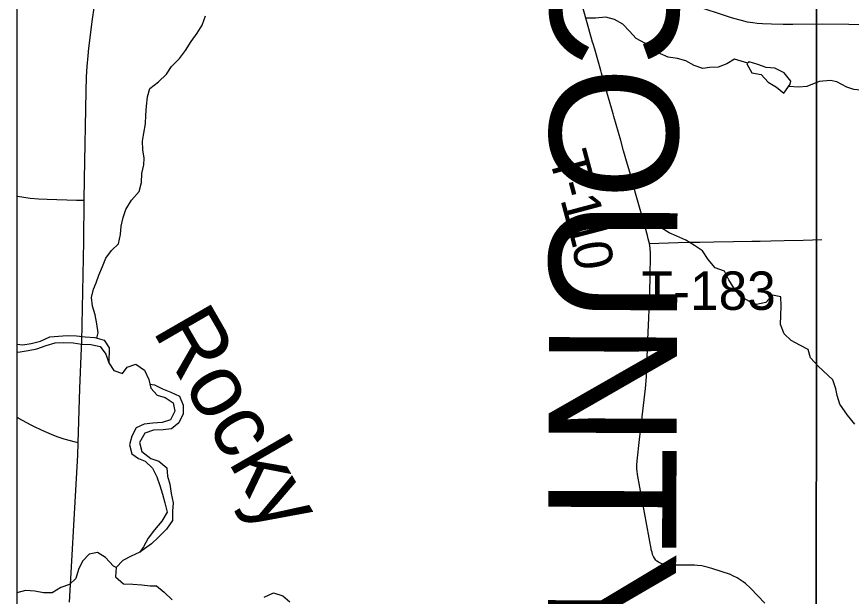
# Model space of a CAD drawing. Extents: x 0 to 34, y 0 to 22.
# Drawn here: x 2.1 to 3.335, y 16.53 to 17.388 of the extents above; entities that cross this region are included whole.
import ezdxf

# ---------------------------------------------------------------- set-up
doc = ezdxf.new("R2010")
doc.units = 0
for name, color, linetype in [('Default', 7, 'Continuous'), ('GM_X_County_Road', 7, 'Continuous'), ('GM_X_County_Text', 7, 'Continuous'), ('GM_X_Minor_Lake', 7, 'Continuous'), ('GM_X_Minor_River', 7, 'Continuous'), ('GM_X_Minor_River_Text', 7, 'Continuous'), ('GM_X_Township_Road', 7, 'Continuous'), ('GM_X_Township_Road_Text', 7, 'Continuous'), ('SH_Cut_Line', 7, 'Continuous'), ('SH_Data', 7, 'Continuous')]:
    doc.layers.add(name, color=color, linetype=linetype)

msp = doc.modelspace()

# ---------------------------------------------------------------- linework, layer by layer
at = {"layer": 'Default'}
msp.add_lwpolyline([(3.2826, 20.9), (2.1, 20.9), (2.1, 15.8248), (3.2829, 15.8433), (3.2832, 16.3898), (3.2835, 17.0107), (3.2837, 17.3796), (3.2907, 18.4315), (3.2904, 19.1173), (3.2901, 19.68), (3.2888, 19.8918), (3.2845, 20.5998), (3.2843, 20.6124)], close=True, dxfattribs=at)
msp.add_lwpolyline([(8.1749, 20.9), (3.2826, 20.9), (3.2843, 20.6124), (3.2845, 20.5998), (3.2888, 19.8918), (3.2901, 19.68), (3.2904, 19.1173), (3.2907, 18.4315), (3.2837, 17.3796), (3.2835, 17.0107), (3.2832, 16.3898), (3.2829, 15.8433), (3.425, 15.8449), (3.4609, 15.8448), (3.6703, 15.8472), (4.3446, 15.8524), (4.6273, 15.8569)], dxfattribs=at)
at = {"layer": 'GM_X_County_Road'}
msp.add_lwpolyline([(2.1781, 16.5218), (2.1849, 16.6442), (2.1903, 16.7391), (2.1912, 16.7577), (2.1934, 16.8382), (2.1958, 16.898), (2.1962, 16.9076), (2.1993, 17.0555), (2.2001, 17.1166), (2.2004, 17.148), (2.2028, 17.2783), (2.2034, 17.2994), (2.2041, 17.3149), (2.2056, 17.3304), (2.2069, 17.3417), (2.2122, 17.3845), (2.2146, 17.4013)], dxfattribs=at)
at = {"layer": 'GM_X_Minor_Lake'}
for points in [[(3.1841, 17.3218), (3.1807, 17.3184), (3.188, 17.3055), (3.2017, 17.303), (3.2121, 17.2913), (3.2247, 17.2839), (3.2351, 17.2752), (3.2448, 17.2883)], [(3.2448, 17.2883), (3.2459, 17.2929), (3.2359, 17.3053), (3.2222, 17.3124), (3.2092, 17.313), (3.197, 17.3174), (3.1841, 17.3218)], [(3.2448, 17.2883), (3.2459, 17.2929), (3.2359, 17.3053), (3.2222, 17.3124), (3.2092, 17.313), (3.197, 17.3174), (3.1841, 17.3218)]]:
    msp.add_lwpolyline(points, dxfattribs=at)
at = {"layer": 'GM_X_Minor_River'}
for points in [[(2.2187, 16.9127), (2.2205, 16.9202), (2.2186, 16.9338), (2.2163, 16.9468), (2.2121, 16.9597), (2.2109, 16.9726), (2.2139, 16.9848), (2.2177, 16.9943), (2.2215, 17.0057), (2.2272, 17.0187), (2.2321, 17.0308), (2.2405, 17.0423), (2.2507, 17.0522), (2.2538, 17.0658), (2.2545, 17.0784), (2.2575, 17.091), (2.2617, 17.1031), (2.2701, 17.1168), (2.2811, 17.1294), (2.2845, 17.1427), (2.2852, 17.1564), (2.2882, 17.1693), (2.2886, 17.1788), (2.2867, 17.1914), (2.2863, 17.2039), (2.2882, 17.2161), (2.2908, 17.2298), (2.2912, 17.2427), (2.2919, 17.256), (2.2938, 17.2697), (2.2968, 17.2823), (2.3101, 17.2922), (2.3219, 17.3032), (2.3291, 17.3147), (2.3409, 17.3265), (2.3496, 17.3383), (2.358, 17.3516), (2.3671, 17.3638), (2.3743, 17.376), (2.3793, 17.3896)], [(3.1819, 17.3197), (3.1624, 17.3253), (3.151, 17.3188), (3.1381, 17.3138), (3.1251, 17.313), (3.1156, 17.3115), (3.1027, 17.3161), (3.0901, 17.3233), (3.0779, 17.3263), (3.0642, 17.3286), (3.0528, 17.3335), (3.041, 17.3399), (3.0296, 17.3494), (3.017, 17.3559), (3.0067, 17.3669), (2.9972, 17.3775), (2.9846, 17.3844), (2.9717, 17.3878), (2.9568, 17.3862), (2.9431, 17.3862)], [(3.4724, 17.3021), (3.4526, 17.2897), (3.4397, 17.2835), (3.4291, 17.2807), (3.4181, 17.2783), (3.4056, 17.2771), (3.3904, 17.2773), (3.3764, 17.2783), (3.365, 17.279), (3.354, 17.2792), (3.3388, 17.2806), (3.3285, 17.2839), (3.314, 17.2922), (3.3045, 17.294), (3.2877, 17.2925)], [(3.2877, 17.2925), (3.2694, 17.2851), (3.2572, 17.2843), (3.2426, 17.2852)], [(3.2862, 16.871), (3.2749, 16.8835), (3.2715, 16.8957), (3.2589, 16.9021), (3.246, 16.9089), (3.2357, 16.9188), (3.2303, 16.9325), (3.2311, 16.9462), (3.2314, 16.9599), (3.231, 16.9736), (3.2188, 16.9762), (3.2086, 16.9652), (3.1949, 16.9621), (3.1835, 16.9674), (3.1705, 16.9746), (3.1618, 16.986), (3.1537, 16.9989), (3.1476, 17.0115), (3.1336, 17.0168), (3.1236, 17.0289), (3.1152, 17.0419), (3.1031, 17.0495), (3.0901, 17.0578), (3.0772, 17.0635), (3.0654, 17.0684), (3.0536, 17.076)], [(2.1, 16.9038), (2.109, 16.9025), (2.1216, 16.9048), (2.1353, 16.9083), (2.149, 16.9144), (2.1619, 16.9155), (2.1748, 16.9163), (2.1885, 16.9159), (2.2011, 16.9144), (2.2156, 16.9137), (2.2293, 16.9095), (2.2369, 16.8981), (2.2365, 16.876)], [(2.1, 16.892), (2.1049, 16.8922), (2.117, 16.8942), (2.13, 16.8968), (2.1437, 16.9014), (2.157, 16.9056), (2.1699, 16.906), (2.1836, 16.9057), (2.1962, 16.9034), (2.2099, 16.903), (2.2236, 16.9004), (2.232, 16.8886), (2.2365, 16.8761), (2.2438, 16.8647), (2.2567, 16.8601), (2.2636, 16.8696), (2.2765, 16.8738), (2.2891, 16.8651), (2.2956, 16.8514), (2.2986, 16.8385), (2.3078, 16.8282), (2.3199, 16.8248), (2.3314, 16.8169), (2.3341, 16.8043), (2.3276, 16.7914), (2.3151, 16.7875), (2.3014, 16.7868), (2.2888, 16.7852), (2.277, 16.7799), (2.2706, 16.7673), (2.2668, 16.7544), (2.2702, 16.7411), (2.2805, 16.7343), (2.29, 16.7305), (2.3011, 16.7202), (2.3072, 16.7073), (2.3118, 16.6944), (2.3156, 16.6818), (2.319, 16.6685), (2.3225, 16.6548), (2.3149, 16.6415), (2.3039, 16.6289), (2.2948, 16.6164), (2.2875, 16.6034)], [(3.3402, 16.7852), (3.3295, 16.7984), (3.3183, 16.8146), (3.3144, 16.8275), (3.3124, 16.8373), (3.3078, 16.8506), (3.2862, 16.8711)], [(2.2972, 16.8446), (2.3039, 16.8434), (2.3157, 16.8377), (2.3283, 16.8324), (2.3409, 16.8267), (2.3462, 16.8134), (2.3466, 16.8005), (2.3398, 16.7872), (2.3291, 16.7781), (2.3166, 16.7769), (2.3025, 16.7761), (2.2896, 16.7719), (2.2816, 16.7582), (2.2854, 16.7449), (2.2984, 16.7343), (2.3106, 16.7305), (2.322, 16.7206), (2.3232, 16.7081), (2.3266, 16.6963), (2.3285, 16.6826), (2.3316, 16.6689), (2.3305, 16.6564), (2.3305, 16.6427), (2.3218, 16.6297), (2.31, 16.6179), (2.2993, 16.608), (2.2823, 16.5956)], [(2.2875, 16.6034), (2.2822, 16.5955), (2.2693, 16.5897), (2.2571, 16.5836), (2.2473, 16.573), (2.2461, 16.5593), (2.2583, 16.549), (2.272, 16.5483), (2.285, 16.5472), (2.2975, 16.546), (2.307, 16.546), (2.3185, 16.5366), (2.3299, 16.5252)], [(2.2473, 16.573), (2.2435, 16.5752), (2.2316, 16.5878), (2.2198, 16.595), (2.2073, 16.5927), (2.1974, 16.5824), (2.1917, 16.5699), (2.1875, 16.5569), (2.178, 16.5478), (2.1651, 16.5436), (2.1526, 16.5356), (2.1396, 16.5356), (2.1267, 16.5378), (2.113, 16.539), (2.1, 16.5353)], [(2.4665, 16.5291), (2.4802, 16.5356), (2.4939, 16.5311), (2.5042, 16.5223)]]:
    msp.add_lwpolyline(points, dxfattribs=at)
at = {"layer": 'GM_X_Township_Road'}
for points in [[(2.9191, 17.4674), (2.9653, 17.4521), (3.0033, 17.4395), (3.0322, 17.4297), (3.0417, 17.4264), (3.0867, 17.4111), (3.1023, 17.4056), (3.1559, 17.3877), (3.1607, 17.3862), (3.1724, 17.3831), (3.1812, 17.381), (3.1853, 17.3802), (3.1897, 17.3797), (3.1958, 17.379), (3.2037, 17.3784), (3.2172, 17.3778), (3.2342, 17.3775), (3.2489, 17.3774), (3.292, 17.3777)], [(3.2074, 16.5203), (3.1862, 16.5424), (3.1784, 16.5493), (3.1752, 16.5518), (3.1707, 16.5549), (3.1663, 16.5576), (3.1601, 16.5608), (3.1565, 16.5624), (3.1289, 16.5716), (3.1219, 16.5736), (3.1138, 16.5754), (3.1078, 16.5762), (3.1029, 16.5765), (3.0761, 16.5766), (3.063, 16.5769), (3.0594, 16.5774), (3.0563, 16.5781), (3.0529, 16.5792), (3.0497, 16.5808), (3.0476, 16.5823), (3.0458, 16.584), (3.0439, 16.5867), (3.0424, 16.5894), (3.0412, 16.5924), (3.0403, 16.5956), (3.0397, 16.5984), (3.0189, 16.7107), (3.0182, 16.7158), (3.018, 16.7191), (3.0179, 16.722), (3.018, 16.7246), (3.0185, 16.7309), (3.0219, 16.7623), (3.0306, 16.8381), (3.0321, 16.8553), (3.0333, 16.8798), (3.0338, 16.9002), (3.0356, 16.942), (3.037, 16.9804), (3.0376, 17.0039), (3.0377, 17.0142), (3.0378, 17.025), (3.0379, 17.031), (3.0378, 17.0383), (3.0373, 17.0457), (3.0364, 17.0527), (3.0356, 17.0562), (3.0348, 17.0595), (3.0336, 17.0644), (3.0259, 17.0924), (3.016, 17.1273), (3.0072, 17.1583), (3.004, 17.1696), (2.9983, 17.1896), (2.9939, 17.205), (2.9837, 17.2408), (2.9827, 17.2444), (2.9806, 17.2515), (2.9735, 17.2765), (2.973, 17.2783), (2.9654, 17.305), (2.9644, 17.3085), (2.9554, 17.3404), (2.9531, 17.3484), (2.9524, 17.3509), (2.9443, 17.3794), (2.9288, 17.4341)], [(3.292, 17.3777), (3.4496, 17.376), (3.6018, 17.3747), (3.7668, 17.3723)], [(2.1, 17.1232), (2.1011, 17.1229), (2.1105, 17.1211), (2.1198, 17.1199), (2.1321, 17.119), (2.1449, 17.1183), (2.1886, 17.1166), (2.2001, 17.1166)], [(3.0364, 17.0527), (3.0502, 17.0531), (3.0934, 17.0545), (3.1109, 17.0547), (3.1318, 17.0549), (3.161, 17.0556), (3.1882, 17.056), (3.2003, 17.0561), (3.2163, 17.0564), (3.2356, 17.0569), (3.264, 17.0577), (3.2918, 17.0584)], [(2.1912, 16.7577), (2.1871, 16.7583), (2.1703, 16.7631), (2.1616, 16.766), (2.1548, 16.7686), (2.1481, 16.7714), (2.1414, 16.7743), (2.1347, 16.7773), (2.1281, 16.7804), (2.1216, 16.7836), (2.1151, 16.787), (2.1087, 16.7904), (2.1023, 16.794), (2.1, 16.7953)]]:
    msp.add_lwpolyline(points, dxfattribs=at)
at = {"layer": 'SH_Cut_Line'}
for points in [[(3.2826, 20.9), (2.1, 20.9), (2.1, 14.1), (3.2807, 14.1), (3.2808, 14.1155), (3.2822, 14.2781), (3.2841, 14.501), (3.2832, 14.8896), (3.2811, 15.7294), (3.2815, 15.7537), (3.2829, 15.8433), (3.2832, 16.3898), (3.2835, 17.0107), (3.2837, 17.3796), (3.2907, 18.4315), (3.2904, 19.1173), (3.2901, 19.68), (3.2888, 19.8918), (3.2845, 20.5998), (3.2843, 20.6124)], [(3.2807, 14.1), (8.9, 14.1), (8.9, 20.9), (3.2826, 20.9), (3.2843, 20.6124), (3.2845, 20.5998), (3.2888, 19.8918), (3.2901, 19.68), (3.2904, 19.1173), (3.2907, 18.4315), (3.2837, 17.3796), (3.2835, 17.0107), (3.2832, 16.3898), (3.2829, 15.8433), (3.2815, 15.7537), (3.2811, 15.7294), (3.2832, 14.8896), (3.2841, 14.501), (3.2822, 14.2781), (3.2808, 14.1155)]]:
    msp.add_lwpolyline(points, close=True, dxfattribs=at)
at = {"layer": 'SH_Data'}
msp.add_line((2.1, 20.9), (2.1, 14.1), dxfattribs=at)

# ---------------------------------------------------------------- texts
at = {"layer": 'GM_X_County_Text'}
msp.add_text('MEDINA COUNTY', height=0.189394, rotation=269.7794, dxfattribs=at).set_placement((2.8942, 18.553))
at = {"layer": 'GM_X_Minor_River_Text'}
msp.add_text('Rocky', height=0.09474, rotation=299.9806, dxfattribs=at).set_placement((2.3001, 16.9238))
at = {"layer": 'GM_X_Township_Road_Text'}
for s, height, rotation, p in [('T', 0.0568, 285.0476, (2.8872, 17.1816)), ('-', 0.0568, 285.0265, (2.8982, 17.1406)), ('1', 0.0568, 284.9539, (2.9043, 17.1181)), ('1', 0.0568, 284.5992, (2.9133, 17.0843)), ('0', 0.0568, 279.0662, (2.9218, 17.0519)), ('T-183', 0.05682, 0, (3.0249, 16.9544))]:
    msp.add_text(s, height=height, rotation=rotation, dxfattribs=at).set_placement(p)

doc.saveas('drawing.dxf')
